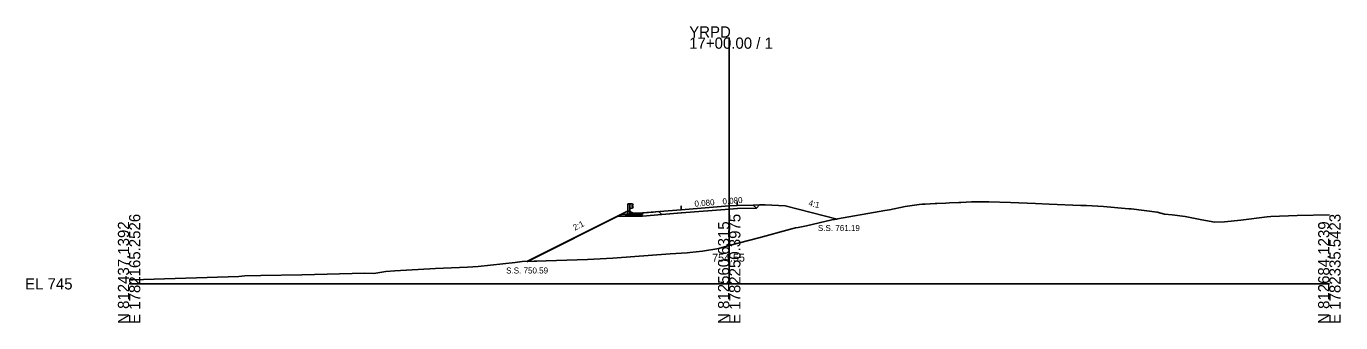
# Model space of a CAD drawing. Extents: x -26 to 1403, y -10 to 9544.
# Drawn here: x -25.7 to 302.8, y 6990.3 to 7064.3 of the extents above; entities that cross this region are included whole.
import ezdxf

# ---------------------------------------------------------------- set-up
doc = ezdxf.new("R2010")
doc.units = 0
for name, color, linetype in [('Exist Cross Section Cell', 7, 'Continuous'), ('Exist XS Center Line Elevation Label', 7, 'Continuous'), ('Exist XS Ground Line', 7, 'Continuous'), ('Prop XS Dump Level', 7, 'Continuous'), ('Prop XS Earthwork Shape', 7, 'Continuous'), ('Prop XS EOT Tick Mark', 7, 'Continuous'), ('Prop XS Finish Grade', 7, 'Continuous'), ('Prop XS Finish Grade CurbGutter', 7, 'Continuous'), ('Prop XS Finish Grade Earthwork', 7, 'Continuous'), ('Prop XS Finish Grade Paved Shoulder', 7, 'Continuous'), ('Prop XS Finish Grade Pavement', 7, 'Continuous'), ('Prop XS Guardrail', 7, 'Continuous'), ('Prop XS Pvmt Edge Slope', 7, 'Continuous'), ('Prop XS SE Text', 7, 'Continuous'), ('Prop XS Side Slope Text', 7, 'Continuous'), ('Prop XS SS Elevation Text', 7, 'Continuous'), ('Prop XS Subgrade CurbGutter', 7, 'Continuous'), ('Prop XS Subgrade Earthwork', 7, 'Continuous')]:
    doc.layers.add(name, color=color, linetype=linetype)

msp = doc.modelspace()

# ---------------------------------------------------------------- linework, layer by layer
at = {"layer": 'Exist Cross Section Cell'}
for p, q in [((150, 7000), (150, 7061.52)), ((0, 7000), (150, 7000)), ((150, 7000), (300, 7000))]:
    msp.add_line(p, q, dxfattribs=at)
at = {"layer": 'Exist XS Ground Line'}
for p, q in [((175.69, 7015.96), (188.92, 7018.33)), ((188.92, 7018.33), (190.1, 7018.53)), ((190.1, 7018.53), (193.98, 7019.36)), ((193.98, 7019.36), (197.5, 7019.82)), ((197.5, 7019.82), (198.23, 7019.91)), ((198.23, 7019.91), (198.99, 7019.91)), ((198.99, 7019.91), (201.45, 7020.04)), ((201.45, 7020.04), (201.9, 7020.06)), ((201.9, 7020.06), (204.13, 7020.14)), ((204.13, 7020.14), (205.02, 7020.2)), ((205.02, 7020.2), (207.42, 7020.31)), ((207.42, 7020.31), (207.91, 7020.34)), ((207.91, 7020.34), (210.59, 7020.46)), ((210.59, 7020.46), (213.63, 7020.48)), ((213.63, 7020.48), (214.86, 7020.51)), ((214.86, 7020.51), (220.34, 7020.31)), ((220.34, 7020.31), (226.58, 7020.08)), ((226.58, 7020.08), (229.94, 7019.94)), ((229.94, 7019.94), (237.88, 7019.61)), ((237.88, 7019.61), (238.86, 7019.57)), ((238.86, 7019.57), (239.29, 7019.55)), ((239.29, 7019.55), (243.59, 7019.29)), ((243.59, 7019.29), (249.9, 7018.76)), ((249.9, 7018.76), (250.46, 7018.72)), ((250.46, 7018.72), (257, 7017.91)), ((257, 7017.91), (258.79, 7017.43)), ((167.23, 7014.09), (169.32, 7014.53)), ((169.32, 7014.53), (175.69, 7015.96)), ((258.79, 7017.43), (260.72, 7017.24)), ((260.72, 7017.24), (263.93, 7016.79)), ((263.93, 7016.79), (268.14, 7015.98)), ((268.14, 7015.98), (271.41, 7015.43)), ((271.41, 7015.43), (273.76, 7015.51)), ((273.76, 7015.51), (277.86, 7015.89)), ((277.86, 7015.89), (284.42, 7016.72)), ((284.42, 7016.72), (285.34, 7016.84)), ((285.34, 7016.84), (291.97, 7017.05)), ((291.97, 7017.05), (300, 7017.23)), ((150, 7009.55), (157.38, 7011.49)), ((157.38, 7011.49), (165.35, 7013.64)), ((165.35, 7013.64), (166.53, 7013.97)), ((166.53, 7013.97), (167.23, 7014.09)), ((135.27, 7007.46), (139.45, 7007.79)), ((139.45, 7007.79), (140.15, 7007.84)), ((140.15, 7007.84), (143.35, 7008.19)), ((143.35, 7008.19), (147.42, 7008.87)), ((147.42, 7008.87), (150, 7009.55)), ((84.55, 7004.2), (87.26, 7004.34)), ((87.26, 7004.34), (96.5, 7005.33)), ((96.5, 7005.33), (98.28, 7005.55)), ((98.28, 7005.55), (104.23, 7005.76)), ((104.23, 7005.76), (114.56, 7006.09)), ((114.56, 7006.09), (120.94, 7006.42)), ((120.94, 7006.42), (135.27, 7007.46)), ((0.92, 7001.01), (27.4, 7001.88)), ((27.4, 7001.88), (28.97, 7001.98)), ((28.97, 7001.98), (32.94, 7002.08)), ((32.94, 7002.08), (43.14, 7002.26)), ((43.14, 7002.26), (58.96, 7002.65)), ((58.96, 7002.65), (61.2, 7002.57)), ((61.2, 7002.57), (64.21, 7003.09)), ((64.21, 7003.09), (66.4, 7003.27)), ((66.4, 7003.27), (76.62, 7003.8)), ((76.62, 7003.8), (84.55, 7004.2)), ((0, 7001), (0.92, 7001.01))]:
    msp.add_line(p, q, dxfattribs=at)
at = {"layer": 'Prop XS Dump Level'}
for p, q in [((138, 7018.49), (150, 7019.45)), ((150, 7019.45), (152, 7019.61))]:
    msp.add_line(p, q, dxfattribs=at)
at = {"layer": 'Prop XS Earthwork Shape'}
msp.add_lwpolyline([(131, 7017.93), (132.4, 7018.04), (133.14, 7017.31), (138.06, 7017.7), (150.06, 7018.66), (152.04, 7018.82), (156.78, 7018.91), (157.58, 7019.72), (159, 7019.75), (164, 7019.45), (177.02, 7016.19), (175.69, 7015.96), (169.32, 7014.53), (167.23, 7014.09), (166.53, 7013.97), (165.35, 7013.64), (157.38, 7011.49), (150, 7009.55), (147.42, 7008.87), (143.35, 7008.19), (140.15, 7007.84), (139.45, 7007.79), (135.27, 7007.46), (120.94, 7006.42), (114.56, 7006.09), (104.23, 7005.76), (99.62, 7005.6), (123, 7017.29)], close=True, dxfattribs=at)
at = {"layer": 'Prop XS EOT Tick Mark'}
for p, q in [((138, 7018.49), (138, 7019.49)), ((152, 7019.61), (152, 7020.61))]:
    msp.add_line(p, q, dxfattribs=at)
at = {"layer": 'Prop XS Finish Grade'}
for p, q in [((122.07, 7016.92), (124.73, 7018.25)), ((125.31, 7017.96), (124.73, 7018.25)), ((156, 7019.69), (157.58, 7019.72))]:
    msp.add_line(p, q, dxfattribs=at)
at = {"layer": 'Prop XS Finish Grade CurbGutter'}
for p, q in [((126, 7017.62), (125.31, 7017.96)), ((128.33, 7017.72), (126, 7017.62))]:
    msp.add_line(p, q, dxfattribs=at)
at = {"layer": 'Prop XS Finish Grade Earthwork'}
for p, q in [((157.58, 7019.72), (159, 7019.75)), ((159, 7019.75), (164, 7019.45)), ((164, 7019.45), (177.02, 7016.19)), ((122.07, 7016.92), (99.41, 7005.59))]:
    msp.add_line(p, q, dxfattribs=at)
at = {"layer": 'Prop XS Finish Grade Paved Shoulder'}
for p, q in [((138, 7018.49), (128.33, 7017.72)), ((152, 7019.61), (156, 7019.69))]:
    msp.add_line(p, q, dxfattribs=at)
at = {"layer": 'Prop XS Finish Grade Pavement'}
for p, q in [((138, 7018.49), (150, 7019.45)), ((150, 7019.45), (152, 7019.61))]:
    msp.add_line(p, q, dxfattribs=at)
at = {"layer": 'Prop XS Guardrail'}
for p, q in [((124.68, 7020.02), (125.18, 7020.02)), ((124.68, 7017.52), (124.68, 7020.02)), ((125.18, 7020.02), (125.68, 7020.02)), ((125.18, 7020.02), (125.18, 7017.52)), ((125.68, 7018.88), (125.18, 7018.88)), ((125.68, 7020.02), (125.97, 7019.82)), ((125.97, 7019.7), (125.68, 7019.5)), ((125.68, 7019.5), (125.68, 7019.4)), ((125.68, 7019.4), (125.97, 7019.2)), ((125.97, 7019.08), (125.68, 7018.88)), ((125.97, 7019.82), (126, 7019.76)), ((126, 7019.76), (125.97, 7019.7)), ((125.97, 7019.2), (126, 7019.14)), ((126, 7019.14), (125.97, 7019.08))]:
    msp.add_line(p, q, dxfattribs=at)
at = {"layer": 'Prop XS Pvmt Edge Slope'}
for p, q in [((156, 7019.69), (156.78, 7018.91)), ((124.31, 7017.3), (123.94, 7016.92)), ((125.31, 7017.3), (124.31, 7017.3))]:
    msp.add_line(p, q, dxfattribs=at)
at = {"layer": 'Prop XS Subgrade CurbGutter'}
for p, q in [((125.31, 7017.3), (125.31, 7017.96)), ((128.33, 7017.72), (128.33, 7017.3)), ((128.33, 7017.3), (125.31, 7017.3))]:
    msp.add_line(p, q, dxfattribs=at)
at = {"layer": 'Prop XS Subgrade Earthwork'}
for p, q in [((138, 7017.7), (128.33, 7016.93)), ((138.06, 7017.7), (150.06, 7018.66)), ((150.06, 7018.66), (152.04, 7018.82)), ((152.04, 7018.82), (156.78, 7018.91)), ((156.78, 7018.91), (157.58, 7019.72)), ((123.94, 7016.92), (122.07, 7016.92)), ((128.33, 7016.92), (123.94, 7016.92)), ((128.33, 7016.93), (128.33, 7016.92))]:
    msp.add_line(p, q, dxfattribs=at)

# ---------------------------------------------------------------- texts
at = {"layer": 'Exist Cross Section Cell'}
for s, p in [('YRPD', (140, 7061.52)), ('17+00.00 / 1', (140, 7058.72)), ('EL 745', (-26, 6998.6))]:
    msp.add_text(s, height=2.8, dxfattribs=at).set_placement(p)
for s, p in [('N 812437.1392', (0, 6990)), ('E 1782165.2526', (2.8, 6990)), ('N 812560.6315', (150, 6990)), ('E 1782250.3975', (152.8, 6990)), ('N 812684.1239', (300, 6990)), ('E 1782335.5423', (302.8, 6990))]:
    msp.add_text(s, height=2.8, rotation=90, dxfattribs=at).set_placement(p)
at = {"layer": 'Exist XS Center Line Elevation Label'}
msp.add_text('754.55', height=2, dxfattribs=at).set_placement((145.74, 7005.55))
at = {"layer": 'Prop XS Dump Level'}
for s, p in [('Case4', (126, 7017.49)), ('Case2', (128.33, 7017.68)), ('Case4', (164, 7019.41))]:
    msp.add_text(s, height=0.04, dxfattribs=at).set_placement(p)
at = {"layer": 'Prop XS SE Text'}
for p in [(141.38, 7019.26), (148.38, 7019.82)]:
    msp.add_text('0.080', height=1.5, rotation=4.5739, dxfattribs=at).set_placement(p)
at = {"layer": 'Prop XS Side Slope Text'}
for s, rotation, p in [('4:1', 345.9638, (169.7, 7019.57)), ('2:1', 26.5651, (111.4, 7013.26))]:
    msp.add_text(s, height=1.5, rotation=rotation, dxfattribs=at).set_placement(p)
at = {"layer": 'Prop XS SS Elevation Text'}
for s, p in [('S.S. 761.19', (172.17, 7013.19)), ('S.S. 750.59', (94.24, 7002.59))]:
    msp.add_text(s, height=1.5, dxfattribs=at).set_placement(p)

doc.saveas('drawing.dxf')
